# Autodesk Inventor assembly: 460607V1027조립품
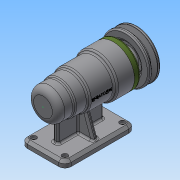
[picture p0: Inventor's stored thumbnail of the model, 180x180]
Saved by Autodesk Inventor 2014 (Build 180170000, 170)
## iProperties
Created: 2016-06
Part Number: 460607V1027조립품
Document SubType Name: Assembly
Designer: NET
Author: NET
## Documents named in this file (11)
- C:\Users\NET\Desktop\460607V1027\460607V1027조립품.iam
- C:\Users\NET\Desktop\460607V1027\460607V1027 부품.ipt
- C:\Users\NET\Desktop\460607V1027\커버.ipt
- C:\Users\NET\Desktop\460607V1027\볼트 M4 x 12.ipt
- C:\Users\NET\Desktop\460607V1027\오일 실.ipt
- C:\Users\NET\Desktop\460607V1027\축.ipt
- C:\Users\NET\Desktop\460607V1027\키 5 x 5 x 16.ipt
- C:\Users\NET\Desktop\460607V1027\베어링 6004.ipt
- C:\Users\NET\Desktop\460607V1027\어댑터슬리브.ipt
- C:\Users\NET\Desktop\460607V1027\베어링 51202.ipt
- C:\Users\NET\Desktop\460607V1027\V벨트풀리.ipt
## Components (7 placed, 3 different names)
1. 460607V1027 부품:3
2. ISO 4762 M4 x 12:5
3. V벨트풀리:1 — 각도:1
4. ISO 4762 M4 x 12:1
5. ISO 4762 M4 x 12:2
6. ISO 4762 M4 x 12:3
7. ISO 4762 M4 x 12:4
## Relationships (1: Angle 1)
- 각도:1 [Angle]: V벨트풀리:1
